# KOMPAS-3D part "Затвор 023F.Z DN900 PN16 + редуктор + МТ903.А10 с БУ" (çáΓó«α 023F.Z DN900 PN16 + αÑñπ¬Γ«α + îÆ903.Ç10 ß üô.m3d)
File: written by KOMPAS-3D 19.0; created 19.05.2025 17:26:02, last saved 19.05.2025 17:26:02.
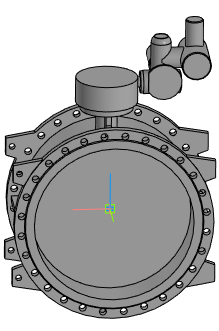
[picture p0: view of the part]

Document properties: Полное имя файла: Затвор 023F.Z DN900 PN16 + редуктор + МТ903.А10 с БУ.a3d

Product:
- Part/product: Затвор 023F.Z DN900 PN16 + редуктор + МТ903.А10 с БУ
    Масса: 1186.95

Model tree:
1. Операция без истории:1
